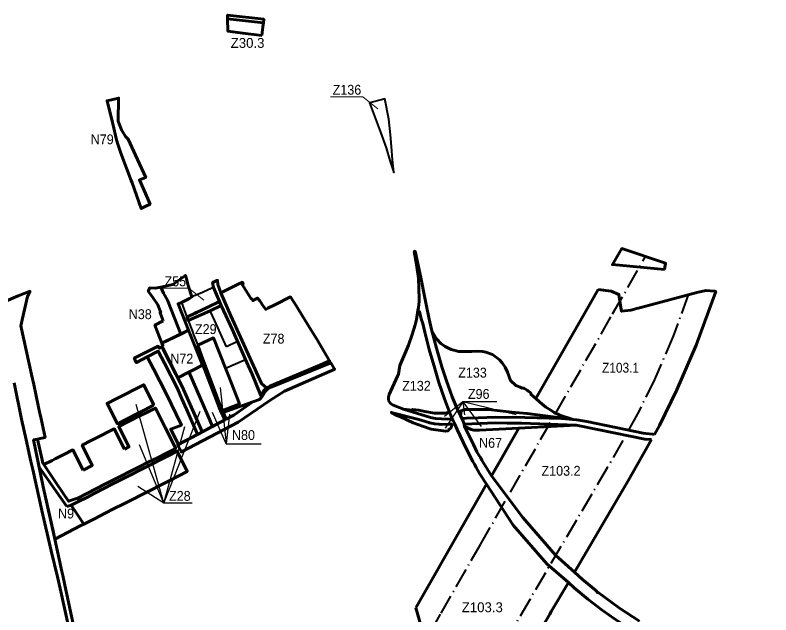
# Model space of a CAD drawing. Extents: x -650277 to -643422, y -1073980 to -1066720.
# Drawn here: x -648765 to -646927, y -1068218 to -1066758 of the extents above; entities that cross this region are included whole.
import ezdxf

# ---------------------------------------------------------------- set-up
doc = ezdxf.new("R2010")
doc.units = 0
doc.header["$LTSCALE"] = 9.6
doc.header["$PDMODE"] = 32
doc.header["$PDSIZE"] = 4.8
doc.linetypes.add('DOT_DASHED', pattern=[7.7, 5, -1.2, 0.3, -1.2])
for name, color, linetype, lineweight in [('1', 7, 'Continuous', 60), ('15', 7, 'Continuous', 60), ('2', 7, 'Continuous', 40), ('3', 7, 'Continuous', 60), ('40', 7, 'Continuous', 60), ('42', 7, 'Continuous', 60), ('45', 7, 'Continuous', 60), ('48', 7, 'Continuous', 60), ('59', 7, 'Continuous', 25), ('60', 7, 'Continuous', 60), ('61', 7, 'Continuous', 60), ('62', 7, 'DOT_DASHED', 40), ('63', 7, 'Continuous', 25), ('7', 7, 'Continuous', 60), ('9', 7, 'Continuous', 60)]:
    doc.layers.add(name, color=color, linetype=linetype, lineweight=lineweight)

msp = doc.modelspace()

# ---------------------------------------------------------------- linework, layer by layer
at = {"layer": '1'}
msp.add_line((-648609.91, -1067940.58), (-648611.61, -1067932.63), dxfattribs=at)
for points in [[(-647708.71, -1067723.99), (-647721.05, -1067691.73), (-647734.63, -1067652.57), (-647744.61, -1067617.96), (-647758.25, -1067571.79), (-647768.5, -1067529.75), (-647773.96, -1067508.48), (-647777.55, -1067496.95), (-647781.85, -1067479.19), (-647785.64, -1067477.02), (-647789.39, -1067498.84), (-647792.54, -1067511.85), (-647799.39, -1067535.48)], [(-647799.39, -1067535.48), (-647808.71, -1067561.03), (-647817.59, -1067582.4)], [(-647704.458, -1067572.034), (-647719.661, -1067564.884), (-647729.802, -1067557.462), (-647740.124, -1067546.265), (-647751.41, -1067526.58), (-647740.49, -1067568.67), (-647727.37, -1067614.33), (-647715.92, -1067648.12), (-647702.04, -1067686.86), (-647690.09, -1067716.05), (-647681.91, -1067732.74), (-647680.804, -1067720.745), (-647672, -1067718), (-647643, -1067718), (-647614, -1067718), (-647557, -1067724), (-647520.145, -1067727.879), (-647408.2, -1067742.37)], [(-647591.227, -1067593.613), (-647604.415, -1067584.047), (-647606.559, -1067583.309), (-647620.586, -1067578.478), (-647628.441, -1067576.759), (-647640.087, -1067576.306), (-647654.743, -1067576.996), (-647685.968, -1067576.68), (-647704.458, -1067572.034)], [(-647817.59, -1067582.4), (-647829.97, -1067610.62), (-647832.8, -1067631.53), (-647835.06, -1067637.01), (-647855.24, -1067681.26), (-647857.51, -1067687.74), (-647856.9, -1067695.97)], [(-647573.605, -1067614.951), (-647580.539, -1067604.432), (-647586.864, -1067597.411), (-647591.227, -1067593.613)], [(-647530.82, -1067666.65), (-647536.83, -1067663.64), (-647547.663, -1067659.519), (-647560.187, -1067647.458), (-647567.744, -1067627.24), (-647573.605, -1067614.951)], [(-647499.095, -1067691.163), (-647503.97, -1067686.73), (-647510.6, -1067680.86), (-647511.24, -1067677.53), (-647517.74, -1067672.85), (-647520.13, -1067671.13), (-647527.76, -1067665.65), (-647530.82, -1067666.65)], [(-647856.9, -1067695.97), (-647852.3, -1067703.36), (-647845.74, -1067707.59), (-647821.02, -1067717.33)], [(-647474.13, -1067711.81), (-647489.3, -1067700.07), (-647499.095, -1067691.163)], [(-648399.64, -1067763.26), (-648424.14, -1067714.34), (-648435.34, -1067720.01), (-648446.58, -1067725.71), (-648468.97, -1067736.91), (-648480.06, -1067742.47), (-648491.14, -1067748.02), (-648513.23, -1067759.38), (-648488.49, -1067808.76), (-648499.7, -1067814.37)], [(-647821.02, -1067717.33), (-647798.5, -1067719.67), (-647798.17, -1067717.58), (-647783.13, -1067719.68), (-647768.53, -1067722.82), (-647745.41, -1067726.6), (-647732.71, -1067727.02), (-647720.45, -1067726.49), (-647708.71, -1067723.99)], [(-647453.87, -1067724.97), (-647462.45, -1067719.84), (-647474.13, -1067711.81)], [(-647408.2, -1067742.37), (-647440.81, -1067731.38), (-647453.87, -1067724.97)], [(-648611.61, -1067932.63), (-648547.09, -1067899.87), (-648530.81, -1067891.61), (-648508.22, -1067880.38), (-648486.09, -1067868.98), (-648463.91, -1067857.74), (-648441.47, -1067846.37), (-648419.44, -1067835.3), (-648397.04, -1067823.85), (-648374.84, -1067812.43), (-648399.64, -1067763.26)], [(-648499.7, -1067814.37), (-648524.44, -1067765.11), (-648535.61, -1067770.85), (-648557.84, -1067782.26), (-648580.14, -1067793.61), (-648602.3, -1067804.83), (-648577.78, -1067854.07), (-648600.14, -1067865.29)], [(-648600.14, -1067865.29), (-648624.76, -1067816.11), (-648645.11, -1067826.48), (-648668.085, -1067838.186), (-648675.26, -1067841.84), (-648695.27, -1067852.04), (-648664.41, -1067897.91)], [(-648572.5, -1067983.59), (-648546.76, -1067970.44), (-648524.72, -1067958.93), (-648502.59, -1067948), (-648480.12, -1067936.55), (-648457.87, -1067925.4), (-648435.55, -1067913.84), (-648413.41, -1067902.53), (-648402.29, -1067897.02), (-648391.08, -1067891.24), (-648368.78, -1067879.75), (-648346.57, -1067868.56), (-648371.27, -1067819.47), (-648393.35, -1067830.81), (-648415.69, -1067841.98), (-648426.65, -1067847.64), (-648437.89, -1067853.4), (-648460.33, -1067864.88), (-648482.5, -1067876.22), (-648504.92, -1067887.52), (-648527.33, -1067898.74), (-648549.44, -1067910.07), (-648571.88, -1067921.71), (-648591.04, -1067931.62), (-648609.91, -1067940.58)], [(-648664.41, -1067897.91), (-648635.249, -1067941.252), (-648620.658, -1067935.93), (-648611.61, -1067932.63)], [(-648609.91, -1067940.58), (-648629.22, -1067950.214), (-648597.93, -1067996.72), (-648572.5, -1067983.59)]]:
    msp.add_lwpolyline(points, dxfattribs=at)
for points in [[(-648397.98, -1067678.79), (-648373.99, -1067728.95), (-648361.08, -1067755.88), (-648387.04, -1067765.67), (-648384.25, -1067771.07), (-648367.811, -1067802.994), (-648321.623, -1067778.399), (-648326, -1067769), (-648337.32, -1067742.59), (-648348.55, -1067716.71), (-648359.6, -1067691.58), (-648371.34, -1067665.08), (-648386.91, -1067634.83), (-648402.02, -1067605.49), (-648417.12, -1067576.17), (-648443.83, -1067589.92), (-648428.7, -1067619.24), (-648413.57, -1067648.57)], [(-648342.697, -1067626.806), (-648369.949, -1067640.851), (-648359.213, -1067661.956), (-648310.511, -1067772.476), (-648285.254, -1067759.008), (-648296.891, -1067732.172), (-648342.023, -1067628.096)], [(-648519.63, -1067691.58), (-648541.86, -1067702.86), (-648516.73, -1067752.57), (-648494.84, -1067741.06), (-648472.5, -1067729.76), (-648450.23, -1067718.32), (-648430.17, -1067708.33), (-648428.67, -1067705.52), (-648452.72, -1067657.62)]]:
    msp.add_lwpolyline(points, close=True, dxfattribs=at)
at = {"layer": '1', "lineweight": 25}
msp.add_lwpolyline([(-648335, -1067946), (-648404, -1067946), (-648353, -1067759)], dxfattribs=at)
at = {"layer": '15'}
msp.add_line((-648264.34, -1067464.83), (-648268.67, -1067455.43), dxfattribs=at)
for points in [[(-648161.58, -1066777.41), (-648160.51, -1066768.4), (-648248.43, -1066758.34), (-648248.77, -1066767.43)], [(-648362.585, -1067534.204), (-648343.41, -1067524.81), (-648369.01, -1067460.52), (-648361, -1067457.36), (-648341.15, -1067448.14), (-648335.38, -1067444.07), (-648344.41, -1067416.04), (-648349.67, -1067396.88), (-648351.06, -1067391.62), (-648352.16, -1067392.42), (-648353.35, -1067393.29), (-648381.48, -1067413.68), (-648410.92, -1067420.63), (-648409.61, -1067423.44), (-648404.29, -1067434.9), (-648394.92, -1067452.23), (-648393.17, -1067455.88)], [(-648237.81, -1067522.42), (-648204.88, -1067596.54), (-648198.39, -1067610.97), (-648193.8, -1067621), (-648189.03, -1067631.71), (-648167.48, -1067683.45), (-648164.79, -1067678.96), (-648163.11, -1067676.17), (-648160.68, -1067671.55), (-648153.98, -1067665.43), (-648166.173, -1067654.853), (-648240.51, -1067489.9), (-648265.197, -1067434.03), (-648265.197, -1067434.03), (-648272.022, -1067413.59), (-648273.008, -1067403.338), (-648279.24, -1067406.38), (-648285.08, -1067409.24), (-648283.21, -1067420.88), (-648268.67, -1067455.43), (-648267.21, -1067458.61), (-648264.34, -1067464.83), (-648253.1, -1067489.23)], [(-648359.6, -1067691.58), (-648348.55, -1067716.71), (-648337.32, -1067742.59), (-648326, -1067769), (-648321.623, -1067778.399), (-648310.511, -1067772.476), (-648323.178, -1067741.953), (-648359.213, -1067661.956), (-648405.054, -1067571.837), (-648408.002, -1067565.219), (-648414.73, -1067568.8), (-648417.19, -1067564.02), (-648475.78, -1067593.11), (-648473.34, -1067598.06), (-648470.57, -1067603.69), (-648470.47, -1067603.64), (-648443.83, -1067589.92), (-648417.12, -1067576.17), (-648402.02, -1067605.49), (-648386.91, -1067634.83), (-648371.34, -1067665.08)], [(-647988.235, -1067619.912), (-647995.04, -1067608.56), (-647997.68, -1067604.11), (-648144.83, -1067664.48), (-648151.6, -1067668.12), (-648157.2, -1067674.32), (-648161, -1067680.96), (-648162.69, -1067684), (-648164.09, -1067686.51), (-648171.21, -1067693.37), (-648187.139, -1067699.179), (-648233.264, -1067731.288), (-648251.711, -1067741.124), (-648258.96, -1067725.37), (-648262.632, -1067726.711), (-648255.016, -1067742.886), (-648319.983, -1067777.526), (-648370.113, -1067804.22), (-648360.993, -1067821.027), (-648222.872, -1067748.412), (-648146.127, -1067695.8), (-648110.36, -1067673.133), (-647988.052, -1067619.624)]]:
    msp.add_lwpolyline(points, close=True, dxfattribs=at)
for points in [[(-648793.71, -1067456.88), (-648757.97, -1067441.51), (-648728.95, -1067430.33), (-648735.59, -1067442.88), (-648748.53, -1067499.3), (-648751.29, -1067514.57), (-648731.06, -1067607.06), (-648725.8, -1067632.36), (-648720.1, -1067657.12), (-648708.26, -1067712.07), (-648706.08, -1067723.56), (-648702.33, -1067740.84), (-648692.53, -1067785.79), (-648704.614, -1067788.491), (-648710.961, -1067789.906), (-648720.34, -1067792), (-648696.93, -1067905.76), (-648672.31, -1068017.25), (-648668.92, -1068032.96), (-648651.89, -1068111.95), (-648649.74, -1068121.95), (-648644.73, -1068145.27), (-648630.99, -1068209.19), (-648610.14, -1068304.32)], [(-648268.67, -1067455.43), (-648297.915, -1067469.319), (-648326.09, -1067482.7), (-648347.51, -1067492.87), (-648344.186, -1067501.627), (-648291.172, -1067477.571), (-648264.34, -1067464.83)], [(-648634.84, -1068248.76), (-648655.88, -1068153.63), (-648662.71, -1068124.76), (-648677.61, -1068061.74), (-648700.16, -1067963.42), (-648722.09, -1067863.84), (-648727.05, -1067844.33), (-648738.7, -1067792.04), (-648749.97, -1067741.49), (-648767.84, -1067652.98)], [(-648710.961, -1067789.906), (-648720.34, -1067792), (-648706.687, -1067858.345), (-648640, -1067954)], [(-648695.27, -1067852.04), (-648697.7, -1067848.43), (-648699.621, -1067840.06), (-648699.593, -1067840.046), (-648710.96, -1067789.91)], [(-648611.61, -1067932.63), (-648620.658, -1067935.93), (-648635.249, -1067941.252), (-648664.41, -1067897.91), (-648695.27, -1067852.04)], [(-648640, -1067954), (-648629.22, -1067950.214), (-648609.91, -1067940.58), (-648611.61, -1067932.63)]]:
    msp.add_lwpolyline(points, dxfattribs=at)
at = {"layer": '2'}
msp.add_line((-648347.51, -1067492.87), (-648326.09, -1067482.7), dxfattribs=at)
for points in [[(-647876.57, -1067043.5), (-647863.04, -1067081.36), (-647853.65, -1067111.91), (-647844.3, -1067141.25), (-647847.09, -1067110.58), (-647850.07, -1067077.71), (-647852.63, -1067049.52), (-647856.11, -1067011.21), (-647866.14, -1066961.98), (-647871.52, -1066963.43), (-647903.5, -1066972.05), (-647903.5, -1066972.05)], [(-648251.33, -1067565.28), (-648279.86, -1067502.11), (-648291.17, -1067477.57), (-648344.186, -1067501.627), (-648334.09, -1067528.2), (-648331.149, -1067535.938), (-648321.36, -1067561.69), (-648282.863, -1067543.596), (-648254.04, -1067616.96), (-648204.88, -1067596.54), (-648224.16, -1067552.55)]]:
    msp.add_lwpolyline(points, close=True, dxfattribs=at)
for points in [[(-648268.67, -1067455.43), (-648283.21, -1067420.88), (-648295.66, -1067426.76), (-648309.57, -1067433.34), (-648335.38, -1067444.07), (-648341.15, -1067448.14)], [(-648341.15, -1067448.14), (-648361, -1067457.36), (-648347.51, -1067492.87)], [(-648326.09, -1067482.7), (-648295.409, -1067468.129), (-648268.67, -1067455.43)]]:
    msp.add_lwpolyline(points, dxfattribs=at)
msp.add_point((-648326.09, -1067482.7), dxfattribs=at)
at = {"layer": '3'}
msp.add_lwpolyline([(-648165.33, -1066807.74), (-648162.8, -1066786.8), (-648161.58, -1066777.41), (-648248.77, -1066767.43), (-648247.78, -1066797.53), (-648211.58, -1066802.18)], close=True, dxfattribs=at)
at = {"layer": '40'}
msp.add_lwpolyline([(-648405.27, -1067502.27), (-648425.5, -1067512.73), (-648408.26, -1067556.58), (-648362.585, -1067534.205), (-648393.17, -1067455.88), (-648394.92, -1067452.23), (-648404.29, -1067434.9), (-648410.92, -1067420.63), (-648425, -1067423.05), (-648437.75, -1067421.99), (-648441.48, -1067429.63), (-648430.4, -1067445.51), (-648418.3, -1067462.86), (-648412.46, -1067477.42), (-648411.25, -1067481.73), (-648412.89, -1067482.55)], close=True, dxfattribs=at)
at = {"layer": '42'}
msp.add_lwpolyline([(-647606.818, -1067879.061), (-647540.208, -1067762.876), (-647635.758, -1067768.38), (-647649.22, -1067768.38), (-647656.469, -1067766.309), (-647672.05, -1067758.98), (-647650.8, -1067803.28), (-647642.29, -1067820.76), (-647637.21, -1067829.29), (-647633.69, -1067834.31), (-647630.3, -1067841.02), (-647625.37, -1067848.86), (-647617.25, -1067861.95)], close=True, dxfattribs=at)
at = {"layer": '45'}
msp.add_lwpolyline([(-648405.41, -1067563.84), (-648408.002, -1067565.219), (-648369.949, -1067640.851), (-648342.697, -1067626.806), (-648328.54, -1067619.51), (-648309.522, -1067609.713), (-648317.43, -1067590), (-648343.41, -1067524.81), (-648408.26, -1067556.58)], close=True, dxfattribs=at)
at = {"layer": '48'}
for points in [[(-648528.01, -1067023.13), (-648518.72, -1067061.99), (-648514.86, -1067074.83), (-648507.88, -1067093.9), (-648483.31, -1067160.63), (-648480.57, -1067166.13), (-648458.73, -1067229.1), (-648449.03, -1067224.14), (-648437.02, -1067217.99), (-648462.97, -1067159.24), (-648447.66, -1067153.25), (-648467.56, -1067110.02), (-648490.23, -1067060.06), (-648496.87, -1067053.5), (-648506.78, -1067037.81), (-648514.38, -1067016.2), (-648513.842, -1066960.243), (-648541.52, -1066966.657)], [(-648342.023, -1067628.096), (-648296.891, -1067732.172), (-648285.254, -1067759.008), (-648255.016, -1067742.886), (-648265.614, -1067720.378), (-648269.27, -1067712.6), (-648308.43, -1067609.15), (-648328.54, -1067619.51), (-648342.697, -1067626.806)], [(-648258.96, -1067725.37), (-648251.711, -1067741.124), (-648233.264, -1067731.288), (-648187.139, -1067699.179)]]:
    msp.add_lwpolyline(points, close=True, dxfattribs=at)
for points in [[(-648265.08, -1067712.06), (-648261.25, -1067720.39), (-648235.78, -1067710.79), (-648219.86, -1067704.42), (-648247.53, -1067633.53), (-648254.04, -1067616.96), (-648282.863, -1067543.596), (-648321.36, -1067561.69)], [(-648321.361, -1067561.69), (-648311.95, -1067586.45), (-648265.08, -1067712.06)]]:
    msp.add_lwpolyline(points, dxfattribs=at)
at = {"layer": '59', "lineweight": 13}
for points in [[(-647998, -1066957), (-647920, -1066957), (-647883, -1066986)], [(-648405, -1067423), (-648343, -1067423), (-648306, -1067452)]]:
    msp.add_lwpolyline(points, dxfattribs=at)
at = {"layer": '60'}
for points in [[(-647606.818, -1067879.061), (-647617.25, -1067861.95), (-647625.37, -1067848.86), (-647630.3, -1067841.02), (-647633.69, -1067834.31), (-647637.21, -1067829.29), (-647642.29, -1067820.76), (-647650.8, -1067803.28), (-647672.05, -1067758.98), (-647673.47, -1067753.48), (-647673.47, -1067753.48), (-647674.67, -1067748.73), (-647676.47, -1067744.5), (-647678.66, -1067739.38), (-647681.91, -1067732.74), (-647690.09, -1067716.05), (-647702.04, -1067686.86), (-647715.92, -1067648.12), (-647727.37, -1067614.33), (-647740.49, -1067568.67), (-647751.41, -1067526.58), (-647756.55, -1067505.32), (-647759.16, -1067494.01), (-647764.89, -1067466.64), (-647768.5, -1067446.04), (-647778.78, -1067397.1), (-647792.52, -1067332.74), (-647794.54, -1067333.14), (-647788.77, -1067365.03), (-647784.55, -1067398.01), (-647782.39, -1067448.34), (-647782.5, -1067455.11), (-647784.36, -1067469.6), (-647785.64, -1067477.02), (-647781.85, -1067479.19), (-647777.55, -1067496.95), (-647773.96, -1067508.48), (-647768.5, -1067529.75), (-647758.25, -1067571.79), (-647744.61, -1067617.96), (-647734.63, -1067652.57), (-647721.05, -1067691.73), (-647708.71, -1067723.99), (-647702.21, -1067740.43), (-647699.89, -1067745.24), (-647697.85, -1067749.46), (-647695.71, -1067753.9), (-647690.19, -1067766.37), (-647668.13, -1067812.76), (-647651.94, -1067844.36), (-647648.33, -1067851.17), (-647643.83, -1067859.13), (-647635.77, -1067873.43), (-647618.773, -1067899.914)], [(-647783.54, -1067742.11), (-647850.45, -1067724.77), (-647838.18, -1067731.62), (-647832.56, -1067734.22), (-647829.49, -1067734.58), (-647796.87, -1067750.25), (-647774.54, -1067758.68), (-647753.53, -1067765.58), (-647718.54, -1067770.6), (-647712.01, -1067769.63), (-647712.26, -1067767.28)], [(-647712.26, -1067767.28), (-647711.773, -1067767.135), (-647711.286, -1067766.968), (-647710.799, -1067766.777), (-647710.315, -1067766.562), (-647709.834, -1067766.324), (-647709.359, -1067766.062), (-647708.892, -1067765.776), (-647708.433, -1067765.466), (-647707.985, -1067765.133), (-647707.55, -1067764.777), (-647707.128, -1067764.398), (-647706.723, -1067763.999), (-647706.335, -1067763.579), (-647705.966, -1067763.14), (-647705.617, -1067762.683), (-647705.29, -1067762.21), (-647704.985, -1067761.721), (-647704.704, -1067761.22), (-647704.447, -1067760.707), (-647704.216, -1067760.184), (-647704.01, -1067759.653), (-647703.83, -1067759.117), (-647703.675, -1067758.576), (-647703.547, -1067758.033), (-647703.445, -1067757.489), (-647703.368, -1067756.946), (-647703.315, -1067756.406), (-647703.287, -1067755.87), (-647703.282, -1067755.341), (-647703.3, -1067754.818), (-647703.34, -1067754.304), (-647703.4, -1067753.8), (-647711.09, -1067753.71), (-647728.98, -1067754.07), (-647734.69, -1067753.66), (-647744.74, -1067752.93), (-647757.74, -1067749.96), (-647759.13, -1067749.54), (-647783.54, -1067742.11)], [(-647405.026, -1068113.904), (-647451.024, -1068071.886), (-647530.038, -1067980.839), (-647606.818, -1067879.061)], [(-647618.773, -1067899.914), (-647553.628, -1067999.427), (-647472.338, -1068093.096), (-647419.713, -1068138.871)], [(-647246.8, -1068233.08), (-647295.47, -1068201.09), (-647347.74, -1068162.54), (-647349.59, -1068163.24), (-647350.6, -1068160.26), (-647353.81, -1068157.67), (-647385.13, -1068131.51), (-647405.026, -1068113.904)], [(-647419.713, -1068138.871), (-647405.71, -1068151.74), (-647372.38, -1068179.01), (-647337.74, -1068205.67), (-647334.62, -1068208.02), (-647307.39, -1068227.44), (-647281.64, -1068244.34), (-647234.11, -1068273.04), (-647230.83, -1068274.93), (-647174.56, -1068306.35), (-647142.788, -1068322.462), (-647130.29, -1068328.8), (-647079.16, -1068357.01), (-647032.91, -1068382.51), (-647029.23, -1068384.46), (-646997.06, -1068401.37), (-646929.56, -1068435.42), (-646927.06, -1068436.66)]]:
    msp.add_lwpolyline(points, dxfattribs=at)
for points in [[(-647754.88, -1067737.59), (-647743.12, -1067739.93), (-647728.29, -1067740.64), (-647713.15, -1067741), (-647702.21, -1067740.43), (-647708.71, -1067723.99), (-647720.45, -1067726.49), (-647732.71, -1067727.02), (-647745.41, -1067726.6), (-647768.53, -1067722.82), (-647783.13, -1067719.68), (-647798.17, -1067717.58), (-647798.5, -1067719.67), (-647821.02, -1067717.33)], [(-647596.91, -1067736.61), (-647572.33, -1067737.03), (-647555.58, -1067736.71), (-647525.685, -1067737.542), (-647436.72, -1067740.02), (-647408.2, -1067742.37), (-647520.145, -1067727.879), (-647557, -1067724), (-647614, -1067718), (-647643, -1067718), (-647672, -1067718), (-647680.804, -1067720.745), (-647681.91, -1067732.74), (-647678.66, -1067739.38), (-647678.66, -1067739.38), (-647667.76, -1067739.01), (-647638.75, -1067738.03)], [(-647540.208, -1067762.876), (-647400.63, -1067756.19), (-647533.597, -1067751.344), (-647555.67, -1067750.91), (-647568.36, -1067750.7), (-647597.83, -1067750.21), (-647673.47, -1067753.48), (-647672.05, -1067758.98), (-647672.05, -1067758.98), (-647656.469, -1067766.309), (-647649.22, -1067768.38), (-647635.758, -1067768.38)]]:
    msp.add_lwpolyline(points, close=True, dxfattribs=at)
at = {"layer": '61'}
msp.add_lwpolyline([(-647185.93, -1067377.38), (-647184.97, -1067372.22), (-647183.09, -1067362.16), (-647289.924, -1067326.309), (-647312.383, -1067365.484)], close=True, dxfattribs=at)
for points in [[(-647346.944, -1067425.768), (-647364.024, -1067455.561), (-647499.095, -1067691.163), (-647489.3, -1067700.07)], [(-647243.39, -1067469.81), (-647252.99, -1067472.35), (-647267.49, -1067476.23), (-647290.23, -1067478.89), (-647292.51, -1067464.56), (-647294.31, -1067453.26), (-647296.75, -1067437.91), (-647315.89, -1067429.71), (-647346.944, -1067425.768)], [(-647061.252, -1067430.908), (-647061.252, -1067430.908), (-647063.45, -1067430.19), (-647064.87, -1067429.73), (-647084.77, -1067428.64), (-647103.55, -1067432.54), (-647243.39, -1067469.81)], [(-647210.537, -1067778.594), (-647198.088, -1067756.5), (-647155.592, -1067670.17), (-647108.971, -1067561.55), (-647061.252, -1067430.908)], [(-647489.3, -1067700.07), (-647474.13, -1067711.81), (-647462.45, -1067719.84), (-647453.87, -1067724.97), (-647440.81, -1067731.38), (-647408.2, -1067742.37), (-647398.74, -1067743.15), (-647374.55, -1067747.34)], [(-647400.63, -1067756.19), (-647540.208, -1067762.876), (-647593.267, -1067855.425), (-647606.818, -1067879.061)], [(-647217.611, -1067791.149), (-647233.83, -1067789.69), (-647345.11, -1067767.28), (-647400.63, -1067756.19)], [(-647374.55, -1067747.34), (-647280.78, -1067766.44), (-647237.91, -1067775.18), (-647231.17, -1067776.55), (-647213.92, -1067778.26), (-647210.537, -1067778.594)], [(-647405.026, -1068113.904), (-647273.297, -1067889.981), (-647217.611, -1067791.149)], [(-647606.818, -1067879.061), (-647530.038, -1067980.839), (-647451.024, -1068071.886), (-647405.026, -1068113.904)], [(-647464.94, -1068215.752), (-647461.188, -1068209.373), (-647419.713, -1068138.871), (-647472.338, -1068093.096), (-647553.628, -1067999.427), (-647618.773, -1067899.914), (-647685.819, -1068016.861)], [(-647685.819, -1068016.861), (-647781.346, -1068183.485), (-647791.055, -1068200.507)], [(-647791.055, -1068200.507), (-647765.22, -1068287.94), (-647759.412, -1068313.436)], [(-647768.02, -1068570.36), (-647770.94, -1068622.47), (-647772.85, -1068656.41), (-647773.08, -1068660.57), (-647773.4, -1068665.71), (-647776.5, -1068714.8), (-647778.95, -1068752.433), (-647675.054, -1068572.919), (-647535.844, -1068336.279), (-647464.94, -1068215.752)]]:
    msp.add_lwpolyline(points, dxfattribs=at)
at = {"layer": '62'}
for points in [[(-647791.193, -1068321.849), (-647729.261, -1068213.27), (-647633.767, -1068046.703), (-647560.654, -1067919.174), (-647311.972, -1067485.403), (-647231.921, -1067345.773)], [(-647128.118, -1067439.088), (-647164.761, -1067539.408), (-647210.113, -1067645.071), (-647251.182, -1067728.502), (-647325.296, -1067860.04), (-647512.903, -1068178.95), (-647726.877, -1068542.68), (-647850.594, -1068756.441), (-647875.691, -1068807.609), (-647903.473, -1068876.174), (-647924.037, -1068940.973), (-647945.559, -1069039.601), (-647956.348, -1069145.994), (-647956.677, -1069214.977), (-647954.925, -1069248.93), (-647950.785, -1069292.731), (-647945.699, -1069329.377), (-647937.748, -1069374.683)]]:
    msp.add_lwpolyline(points, dxfattribs=at)
at = {"layer": '63'}
for p, q in [((-647676, -1067699), (-647672, -1067731)), ((-647676, -1067699), (-647632, -1067759)), ((-648404, -1067946), (-648471, -1067706)), ((-648404, -1067946), (-648315, -1067722)), ((-648404, -1067946), (-648463, -1067804))]:
    msp.add_line(p, q, dxfattribs=at)
for points in [[(-648267, -1067664), (-648252, -1067801), (-648285, -1067725)], [(-647594, -1067699), (-647676, -1067699), (-647721, -1067735)], [(-647547, -1067731), (-647676, -1067699), (-647719, -1067763)], [(-648244, -1067729), (-648252, -1067801), (-648167, -1067801)], [(-648335, -1067946), (-648404, -1067946), (-648467, -1067905)]]:
    msp.add_lwpolyline(points, dxfattribs=at)
at = {"layer": '7'}
msp.add_lwpolyline([(-648640, -1067954), (-648706.687, -1067858.345), (-648696.93, -1067905.76), (-648668.92, -1068032.96), (-648605.323, -1068000.463), (-648597.93, -1067996.72), (-648629.22, -1067950.214)], close=True, dxfattribs=at)
at = {"layer": '9'}
msp.add_lwpolyline([(-648153.98, -1067665.43), (-648149.933, -1067663.646), (-648146.21, -1067661.3), (-648023.96, -1067610.13), (-648000.63, -1067599.14), (-648031.77, -1067546.6), (-648045.04, -1067525.15), (-648076.32, -1067474.6), (-648081.31, -1067466.54), (-648095.28, -1067444.06), (-648133.56, -1067463.2), (-648150.46, -1067471.66), (-648155.85, -1067474.35), (-648164.24, -1067462.15), (-648166.97, -1067458.18), (-648170.38, -1067453.23), (-648175.94, -1067446.89), (-648187.44, -1067452.8), (-648190.23, -1067447.83), (-648191.46, -1067448.59), (-648213.34, -1067413.46), (-648210.48, -1067411.68), (-648211.08, -1067410.6), (-648212.32, -1067408.39), (-648224.19, -1067414.14), (-648265.197, -1067434.03), (-648240.51, -1067489.9), (-648240.51, -1067489.9), (-648166.173, -1067654.853)], close=True, dxfattribs=at)

# ---------------------------------------------------------------- texts
at = {"layer": '59', "width": 0.95}
for s, p in [('Z136', (-647993, -1066952)), ('Z55', (-648402, -1067418)), ('Z29', (-648327.915, -1067534.341))]:
    msp.add_text(s, height=24, dxfattribs=at).set_placement(p)
at = {"layer": '63'}
for s, p in [('Z30.3', (-648241, -1066838)), ('Z103.3', (-647679, -1068211))]:
    msp.add_text(s, height=24, dxfattribs=at).set_placement(p)
for s, width, p in [('N79', 0.95, (-648581.544, -1067072.648)), ('N38', 0.95, (-648489, -1067498)), ('Z78', 0.95, (-648162.836, -1067557.421)), ('N72', 0.95, (-648388, -1067606)), ('Z103.1', 0.9, (-647337.666, -1067628.26)), ('Z133', 0.95, (-647687.579, -1067640.215)), ('Z132', 0.95, (-647823.879, -1067672.215)), ('Z96', 0.95, (-647664, -1067692)), ('N80', 0.95, (-648238, -1067792)), ('N67', 0.95, (-647636.885, -1067811.038)), ('Z103.2', 0.95, (-647485, -1067879)), ('Z28', 0.95, (-648391, -1067940)), ('N9', 0.95, (-648661, -1067983))]:
    msp.add_text(s, height=24, dxfattribs=dict(at, width=width)).set_placement(p)

doc.saveas('drawing.dxf')
